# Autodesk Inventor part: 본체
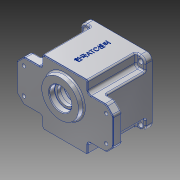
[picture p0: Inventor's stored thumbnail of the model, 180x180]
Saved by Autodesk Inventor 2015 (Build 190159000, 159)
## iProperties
Created: 2016-02
Part Number: 본체
Material: Aluminum 6061
Document SubType Name: Modeling
Designer: Administrator
Density: 2.7 g/cm^3
Appearance: Aluminum - Flat
Mass: 874.359 g
Surface Area: 761.959 cm^2
Volume: 323.837 cm^3
Author: Administrator
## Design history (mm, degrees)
sketch "Sketch1"
  geometry: L1 (33, 30)-(33, 47); L2 (33, 47)-(-33, 47); L3 (-33, 47)-(-33, 30); L4 (-33, 30)-(-70, 30); L5 (-70, 30)-(-70, -30); L6 (-70, -30)-(-33, -30); L7 (-33, -30)-(-33, -47); L8 (-33, -47)-(33, -47); L9 (33, -47)-(33, -30); L10 (33, -30)-(70, -30); L11 (70, -30)-(70, 30); L12 (70, 30)-(33, 30); 2 further points
  constraints: 24 end point, 10 perpendicular, 2 vertical alignment, 1 horizontal, 1 horizontal alignment, 1 midpoint, 1 point on line, 1 vertical
  dimensions: "d11" = 140 distance between parallel lines of L5 L11; "d12" = 70 distance from line of L11 point (0, 0); "d13" = 66 distance of L1.end L2.end; "d14" = 66 distance of L7.end L8.end; "d15" = 94 distance between parallel lines of L8 L2; "d16" = 47 distance from line of L2 point (0, 0); "d17" = 60 distance between parallel lines of L6 L4; "d18" = 30 distance from line of point (0, 0) L4
extrude "Extrusion1" new body sketch "Sketch1" distance "d19" = 13; taper "d20" = 0 deg
chamfer "Chamfer1" distance "d21" = 10; stored, may be unused: second distance "d22" = 2, angle "d23" = 45 deg
sketch "Sketch2"
  geometry: L1 (47, -47)-(-47, -47); L2 (-47, -47)-(-47, 47); L3 (-47, 47)-(47, 47); L4 (47, 47)-(47, -47); L5 (47, -47)-(-47, 47); L6 (-47, -47)-(47, 47); 1 further point
  constraints: 12 end point, 2 midpoint, 2 parallel, 1 horizontal, 1 perpendicular
  dimensions: "d24" = 94 distance of L2.end L3.end; "d25" = 94 distance of L1.end L2.end
extrude "Extrusion2" join sketch "Sketch2" distance "d26" = 67; taper "d27" = 0 deg
sketch "Sketch3"
  geometry: L1 (-47, 30)-(-33, 30) reference; L2 (-33, 30)-(-33, 47) reference; L3 (-33, 47)-(-47, 47) reference; L4 (-47, 47)-(-47, 30) reference; L5 (-33, -47)-(-33, -30) reference; L6 (-33, -30)-(-47, -30) reference; L7 (-47, -30)-(-47, -47) reference; L8 (-47, -47)-(-33, -47) reference; L9 (33, -30)-(33, -47) reference; L10 (33, -47)-(47, -47) reference; L11 (47, -47)-(47, -30) reference; L12 (47, -30)-(33, -30) reference; L13 (33, 30)-(47, 30) reference; L14 (47, 30)-(47, 47) reference; L15 (47, 47)-(33, 47) reference; L16 (33, 47)-(33, 30) reference; 1 further point
extrude "Extrusion3" cut sketch "Sketch3" distance "d28" = 57; taper "d29" = 0 deg
fillet "Fillet1" dims "d30" = 8
sketch "Sketch4"
  geometry: L1 (-47, 30)-(-47, 39) reference; L2 (-33, 30)-(-47, 30) reference; L3 (-33, 47)-(-33, 30) reference; L4 (-39, 47)-(-33, 47) reference; L5 (-33, -47)-(-39, -47) reference; L6 (-33, -30)-(-33, -47) reference; L7 (-47, -30)-(-33, -30) reference; L8 (-47, -39)-(-47, -30) reference; L9 (47, -30)-(47, -39) reference; L10 (33, -30)-(47, -30) reference; L11 (33, -47)-(33, -30) reference; L12 (39, -47)-(33, -47) reference; L13 (33, 47)-(39, 47) reference; L14 (33, 30)-(33, 47) reference; L15 (47, 30)-(33, 30) reference; L16 (47, 39)-(47, 30) reference; C1 r 3.5 at (-40, 40); C2 r 3.5 at (-40, -40); C3 r 3.5 at (40, 40); C4 r 3.5 at (40, -40); A1 r 8 centre (-39, 39) between (-39, 47) and (-47, 39) reference; A2 r 8 centre (-39, -39) between (-47, -39) and (-39, -47) reference; A3 r 8 centre (39, -39) between (39, -47) and (47, -39) reference; A4 r 8 centre (39, 39) between (47, 39) and (39, 47) reference; 1 further point
  constraints: 4 centre point
  dimensions: "d130" = 7 diameter of C1; "d131" = 7 diameter of C2; "d132" = 7 diameter of C3; "d133" = 7 diameter of C4; "d134" = 80 distance of C4.centre C3.centre; "d135" = 40 horizontal distance of point (0, 0) C3.centre; "d136" = 40 horizontal distance of C3.centre point (0, 0); "d137" = 40 horizontal distance of C4.centre point (0, 0); "d138" = 80 distance of C3.centre C1.centre; "d139" = 80 distance of C2.centre C1.centre; "d140" = 40 horizontal distance of point (0, 0) C1.centre; "d141" = 40 horizontal distance of point (0, 0) C2.centre
  node "Projected Loop5"
  node "Projected Loop6"
  node "Projected Loop7"
  node "Projected Loop8"
sketch "Sketch5"
  geometry: C1 r 28 at (0, 11); 1 further point
  constraints: 1 centre point, 1 vertical alignment
  dimensions: "d37" = 56 diameter of C1; "d38" = 11 distance of point (0, 0) C1.centre
extrude "Extrusion5" join sketch "Sketch5" distance "d39" = 7; taper "d40" = -10 deg
sketch "Sketch6"
  geometry: C1 r 26.766 at (0, 0) reference; C2 r 16 at (0, 0); 1 further point
  constraints: 1 centre point, 1 coincident
  dimensions: "d41" = 32 diameter of C2
extrude "Extrusion6" cut sketch "Sketch6" distance "d42" = 8; taper "d43" = 0 deg
hole "Hole1" diameter "d46" = 25; stored, may be unused: countersink angle "d50" = 90 deg, drill point angle "d52" = 0 deg; dims "d44" = 10, "d45" = 10, "d47" = 6, "d48" = 25, "d49" = 5, "d51" = 5
sketch "Sketch7"
  geometry: C1 r 43 at (0, 0); 1 further point
  constraints: 1 centre point, 1 coincident
  dimensions: "d53" = 86 diameter of C1
extrude "Extrusion7" cut sketch "Sketch7" distance "d54" = 9; taper "d55" = 0 deg
sketch "Sketch8"
  geometry: C1 r 40 at (0, 0); 1 further point
  constraints: 1 centre point, 1 coincident
  dimensions: "d56" = 80 diameter of C1
extrude "Extrusion8" cut sketch "Sketch8" distance "d57" = 62; taper "d58" = 0 deg
sketch "Sketch10"
  geometry: A1 r 40 centre (0, 0) between (39.148, 8.214) and (39.148, -8.214) reference; A2 r 36 centre (0, 0) between (36, 0) and (35.778, 3.995); A3 r 4 centre (36, 0) between (35.852, 3.997) and (35.852, -3.997); A4 r 3.5 centre (35.722, -7.495) between (39.148, -8.214) and (35.778, -3.995); A5 r 3.5 centre (35.722, 7.495) between (35.778, 3.995) and (39.148, 8.214); 1 further point
  constraints: 13 point on circle, 4 centre point, 4 tangent, 1 coincident, 1 horizontal alignment
  dimensions: "d63" = 36 radius of A2; "d64" = 4 radius of A3; "d65" = 3.5 radius of A4; "d66" = 3.5 radius of A5
extrude "Extrusion9" join sketch "Sketch10" stored distance "d67" = 62; taper "d68" = 0 deg
mirror "Mirror1"
sketch "Sketch11"
  geometry: C1 r 21 at (0, -11); C2 r 15 at (0, 20); 1 further point
  constraints: 2 centre point, 2 vertical alignment
  dimensions: "d69" = 21 radius of C1; "d70" = 15 radius of C2; "d71" = 11 distance of point (0, 0) C1.centre; "d72" = 20 distance of C2.centre point (0, 0)
extrude "Extrusion10" join sketch "Sketch11" distance "d73" = 7; taper "d74" = 0 deg
sketch "Sketch12"
  geometry: A1 r 4 centre (36, 0) between (35.852, 3.997) and (35.852, -3.997) reference; A2 r 4 centre (-36, 0) between (-35.852, -3.997) and (-35.852, 3.997) reference; 1 further point
hole "Hole2" sketch "Sketch12" at (36, 0), (-36, 0) diameter "d75" = 3.242; stored, may be unused: countersink angle "d79" = 82 deg, drill point angle "d81" = 118 deg; dims "d76" = 7, "d77" = 3.023, "d78" = 5, "d80" = 9
sketch "Sketch13"
  geometry: C1 r 17.5 at (0, -11); A1 r 21 centre (0, -11) between (-8.978, 7.984) and (8.978, 7.984) reference; 1 further point
  constraints: 1 centre point, 1 coincident
  dimensions: "d83" = 35 diameter of C1
extrude "Extrusion11" cut sketch "Sketch13" distance "d84" = 10; taper "d85" = 0 deg
sketch "Sketch14"
  geometry: C1 r 11 at (0, 20); A1 r 15 centre (0, 20) between (8.978, 7.984) and (-8.978, 7.984) reference; 1 further point
  constraints: 1 centre point, 1 coincident
  dimensions: "d87" = 22 diameter of C1
extrude "Extrusion12" cut sketch "Sketch14" distance "d88" = 7; taper "d89" = 0 deg
sketch "Sketch15"
  geometry: C1 r 26.766 at (0, -31) reference; C2 r 11 at (0, 0) reference; C3 r 9.5 at (0, 0); 1 further point
  constraints: 1 centre point, 1 coincident
  dimensions: "d91" = 19 diameter of C3
extrude "Extrusion13" cut sketch "Sketch15" distance "d92" = 1; taper "d93" = 0 deg
sketch "Sketch16"
  geometry: C1 r 12.5 at (0, 11) reference; 5 further points
  constraints: 2 horizontal alignment, 2 vertical alignment
  dimensions: "d94" = 38 distance of point (60, -19) point (60, 19); "d95" = 60 horizontal distance of point (60, 19) C1.centre; "d97" = 19 vertical distance of point (60, 19) point (0, 0); "d98" = 60 horizontal distance of C1.centre point (-60, 19)
hole "Hole3" sketch "Sketch16" at (-60, 19), (-60, -19), (60, 19), (60, -19) diameter "d99" = 5; stored, may be unused: countersink angle "d103" = 82 deg, drill point angle "d105" = 0 deg; dims "d100" = 7, "d101" = 22, "d102" = 7, "d104" = 9
sketch "Sketch17"
  geometry: C1 r 2.5 at (60, -19) reference; C2 r 2.5 at (60, 19) reference; C3 r 2.5 at (-60, 19) reference; C4 r 2.5 at (-60, -19) reference; C5 r 4.5 at (60, -19); C6 r 4.5 at (60, 19); C7 r 4.5 at (-60, -19); C8 r 4.5 at (-60, 19); 1 further point
  constraints: 4 centre point, 4 coincident
  dimensions: "d106" = 9 diameter of C5; "d107" = 9 diameter of C6; "d108" = 9 diameter of C7; "d109" = 9 diameter of C8
extrude "Extrusion14" cut sketch "Sketch17" distance "d110" = 4; taper "d111" = 0 deg
fillet "Fillet2" dims "d112" = 2
sketch "Sketch18"
  geometry: L1 (-33, 30)-(-33, 47) reference; L2 (-60, 30)-(-33, 30) reference; L3 (-70, 20)-(-60, 30) reference; L4 (-70, -20)-(-70, 20) reference; L5 (-60, -30)-(-70, -20) reference; L6 (-33, -30)-(-60, -30) reference; L7 (-33, -47)-(-33, -30) reference; L8 (33, -47)-(-33, -47) reference; L9 (33, -30)-(33, -47) reference; L10 (60, -30)-(33, -30) reference; L11 (70, -20)-(60, -30) reference; L12 (70, 20)-(70, -20) reference; L13 (60, 30)-(70, 20) reference; L14 (33, 30)-(60, 30) reference; L15 (33, 47)-(33, 30) reference; L16 (-33, 47)-(33, 47) reference; L17 (32, 46)-(32, 34); L18 (37, 29)-(57.515, 29); L19 (61.05, 27.536)-(69, 19.586); L20 (69, 19.586)-(69, -17.515); L21 (67.536, -21.05)-(61.05, -27.536); L22 (57.515, -29)-(37, -29); L23 (32, -34)-(32, -46); L24 (32, -46)-(-32, -46); L25 (-32, -46)-(-32, -34); L26 (-37, -29)-(-59.586, -29); L27 (-59.586, -29)-(-69, -19.586); L28 (-69, -19.586)-(-69, 19.586); L29 (-69, 19.586)-(-59.586, 29); L30 (-59.586, 29)-(-37, 29); L31 (-32, 34)-(-32, 46); L32 (-32, 46)-(32, 46); C1 r 28 at (0, 11) reference; C2 r 2.5 at (60, -19) reference; C3 r 2.5 at (-60, -19) reference; C4 r 2.5 at (-60, 19) reference; C5 r 2.5 at (60, 19) reference; A1 r 5 centre (-37, 34) between (-37, 29) and (-32, 34); A2 r 5 centre (-37, -34) between (-32, -34) and (-37, -29); A3 r 5 centre (37, -34) between (37, -29) and (32, -34); A4 r 5 centre (37, 34) between (32, 34) and (37, 29); A5 r 5 centre (57.515, 24) between (61.05, 27.536) and (57.515, 29); A6 r 5 centre (64, -17.515) between (67.536, -21.05) and (69, -17.515); A7 r 5 centre (57.515, -24) between (57.515, -29) and (61.05, -27.536); 8 further points
  constraints: 32 end point, 14 point on circle, 14 point on line, 14 tangent, 7 centre point, 5 equal radius, 15 other
  dimensions: "d148" = 1 distance between parallel lines of L16 L32; "d153" = 5 radius of A1; "d154" = 5 radius of A5
  node "Projected Loop14"
fillet "Fillet3" dims "d116" = 2
fillet "Fillet4" dims "d117" = 3
fillet "Fillet5" dims "d118" = 2
fillet "Fillet6" dims "d119" = 0.3
sketch "Sketch19"
  geometry: L1 (0, 0)-(78, 0) reference; 2 further points
  constraints: 1 vertical alignment, 1 other
  dimensions: "d120" = 40 distance from line of L1 point (39, -40)
emboss "Emboss1" sketch "Sketch19" dims "d121" = 0.5, "d122" = 0
fillet "Fillet7" dims "d123" = 5
fillet "Fillet8" dims "d124" = 5
fillet "Fillet10" dims "d126" = 2
chamfer "Chamfer2" distance "d127" = 1; stored, may be unused: second distance "d128" = 2, angle "d129" = 45 deg
extrude "Extrusion16" cut sketch "Sketch4" stored distance "d142" = 1; taper "d143" = 0 deg
fillet "Fillet11" dims "d144" = 2
extrude "Extrusion17" cut sketch "Sketch18" distance "d149" = 1; taper "d150" = 0 deg
fillet "Fillet12" dims "d151" = 5
fillet "Fillet13" dims "d152" = 5
fillet "Fillet14" dims "d155" = 2
chamfer "Chamfer3" distance "d157" = 1; stored, may be unused: second distance "d158" = 2, angle "d159" = 45 deg
body "Solid1"
node "Projected Loop1"
node "Projected Loop2"
node "Projected Loop3"
node "Projected Loop4"
workplane "Work Plane1"
node "Projected Loop10"
node "Projected Loop11"
node "Projected Loop12"
node "Projected Loop13"
